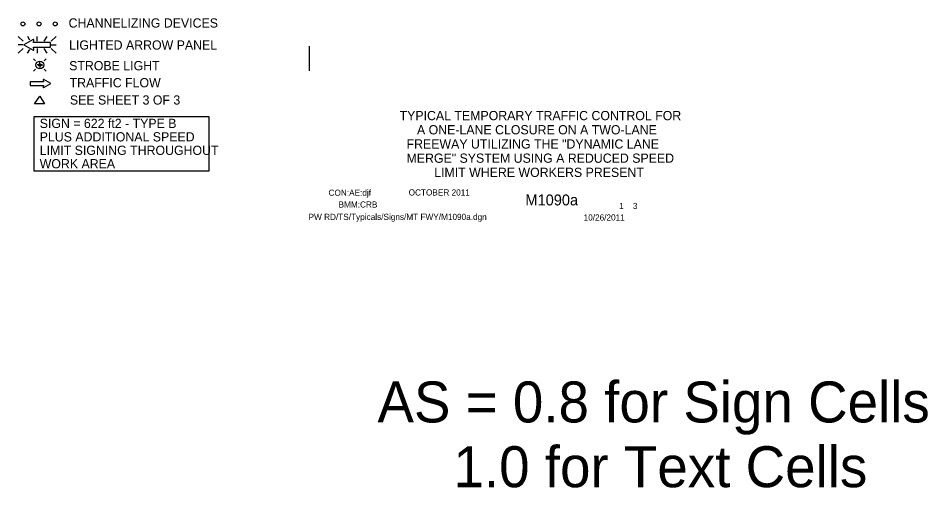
# Model space of a CAD drawing. Extents: x 15278 to 18126, y 1908 to 6555.
# Drawn here: x 15297 to 16214, y 1908 to 2381 of the extents above; entities that cross this region are included whole.
import ezdxf

# ---------------------------------------------------------------- set-up
doc = ezdxf.new("R2010")
doc.units = 0
for name, color, linetype in [('ALI_LEGAL_EX', 7, 'Continuous'), ('BORDER_SIGNAL_WO', 7, 'Continuous'), ('MT_SCRATCH_LEVEL_E', 7, 'Continuous'), ('TRAFFIC_SIGNS_PR', 7, 'Continuous'), ('TYPICAL_TEXT_DIMEN_EX', 7, 'Continuous'), ('TYPICAL_TEXT_DIMEN_PR', 7, 'Continuous')]:
    doc.layers.add(name, color=color, linetype=linetype)

msp = doc.modelspace()

# ---------------------------------------------------------------- linework, layer by layer
at = {"layer": 'ALI_LEGAL_EX'}
msp.add_lwpolyline([(15590.81, 2328.27), (15590.81, 2353.27)], dxfattribs=at)
at = {"layer": 'MT_SCRATCH_LEVEL_E'}
for p, q in [((15322.49, 2317.37), (15309.23, 2317.37)), ((15309.23, 2317.37), (15309.23, 2313.63)), ((15309.23, 2313.63), (15322.49, 2313.63)), ((15322.17, 2319.15), (15322.49, 2317.37)), ((15322.49, 2313.63), (15322.17, 2311.85)), ((15330.1, 2315.52), (15322.86, 2319.63)), ((15322.86, 2311.37), (15330.1, 2315.52))]:
    msp.add_line(p, q, dxfattribs=at)
for centre, start, end in [((15322.63, 2319.22), 60.42484, 189.96381), ((15322.63, 2311.78), 170.03619, 299.77312)]:
    msp.add_arc(centre, 0.463, start, end, dxfattribs=at)
at = {"layer": 'TRAFFIC_SIGNS_PR'}
for p, q in [((15297.1, 2362.98), (15302.03, 2358.05)), ((15308.86, 2359.16), (15306.66, 2362.99)), ((15316.18, 2358.05), (15316.18, 2362.99)), ((15323.42, 2358.05), (15326.27, 2362.99)), ((15330.33, 2358.05), (15335.27, 2362.99)), ((15302.03, 2354.49), (15297.1, 2354.49)), ((15297.1, 2346.01), (15302.03, 2350.94)), ((15306.61, 2346), (15308.72, 2349.67)), ((15316.18, 2350.94), (15316.18, 2346)), ((15326.31, 2346), (15323.46, 2350.94)), ((15330.33, 2354.49), (15335.27, 2354.49)), ((15330.33, 2350.94), (15335.27, 2346)), ((15314.69, 2338.46), (15312.66, 2340.49)), ((15323.25, 2338.46), (15325.29, 2340.49)), ((15314.69, 2329.9), (15312.66, 2327.87)), ((15318.97, 2334.18), (15316.09, 2334.18)), ((15318.97, 2334.18), (15318.97, 2337.06)), ((15318.97, 2334.18), (15318.97, 2330.24)), ((15318.97, 2334.18), (15321.85, 2334.18)), ((15325.29, 2327.87), (15323.25, 2329.9))]:
    msp.add_line(p, q, dxfattribs=at)
for points in [[(15312.11, 2359.77), (15302.82, 2354.49), (15312.11, 2349.17)], [(15312.99, 2349.8), (15312.59, 2352.07), (15329.6, 2352.07), (15329.6, 2356.87), (15312.59, 2356.87), (15312.99, 2359.15)]]:
    msp.add_lwpolyline(points, dxfattribs=at)
for centre, radius in [((15301.84, 2375.58), 2), ((15318.14, 2375.58), 2), ((15334.44, 2375.58), 2), ((15318.97, 2334.18), 3.94), ((15318.97, 2334.18), 1.28)]:
    msp.add_circle(centre, radius, dxfattribs=at)
for centre, radius, start, end in [((15312.4, 2359.25), 0.598, 350.73078, 118.89165), ((15312.4, 2349.7), 0.597, 241.48329, 9.95933)]:
    msp.add_arc(centre, radius, start, end, dxfattribs=at)
at = {"layer": 'TYPICAL_TEXT_DIMEN_EX'}
msp.add_lwpolyline([(15313.2, 2282.41), (15489.3, 2282.41), (15489.3, 2227.3), (15313.2, 2227.3)], close=True, dxfattribs=at)
at = {"layer": 'TYPICAL_TEXT_DIMEN_PR'}
msp.add_lwpolyline([(15313.43, 2294.94), (15318.89, 2302.82), (15323.52, 2294.94)], close=True, dxfattribs=at)

# ---------------------------------------------------------------- texts
at = {"layer": 'BORDER_SIGNAL_WO'}
for s, height, p in [('TYPICAL TEMPORARY TRAFFIC CONTROL FOR', 9.3, (15681.73, 2278.54)), ('A ONE-LANE CLOSURE ON A TWO-LANE', 9.3, (15699.24, 2264.24)), ('FREEWAY UTILIZING THE "DYNAMIC LANE', 9.3, (15688.74, 2249.94)), ('MERGE" SYSTEM USING A REDUCED SPEED', 9.3, (15688.7, 2235.64)), ('LIMIT WHERE WORKERS PRESENT', 9.3, (15716.6, 2221.34)), ('CON:AE:djf  ', 6.2, (15610.05, 2202.35)), ('    OCTOBER 2011    ', 6.2, (15681.62, 2202.63)), ('    M1090a   ', 11, (15792.22, 2192.67)), ('BMM:CRB   ', 6.2, (15620.17, 2190.46)), (' 1    3 ', 6.2, (15900.81, 2188.99)), ('PW RD/TS/Typicals/Signs/MT FWY/M1090a.dgn      ', 6.2, (15589.92, 2178)), ('10/26/2011    ', 6.2, (15867.29, 2177.42)), ('AS = 0.8 for Sign Cells', 41.2877, (15659.37, 1973.92)), ('     1.0 for Text Cells', 41.2877, (15659.37, 1908.64))]:
    msp.add_text(s, height=height, dxfattribs=at).set_placement(p)
at = {"layer": 'TYPICAL_TEXT_DIMEN_EX'}
for s, p in [('CHANNELIZING DEVICES', (15347.92, 2371.9)), ('LIGHTED ARROW PANEL', (15348.45, 2349.67)), ('STROBE LIGHT', (15348.5, 2328.86)), ('TRAFFIC FLOW', (15348.96, 2311.69)), ('SEE SHEET 3 OF 3', (15349.26, 2294.29)), ('SIGN = 622 ft2 - TYPE B', (15318.8, 2270.67)), ('PLUS ADDITIONAL SPEED', (15318.8, 2257.12)), ('LIMIT SIGNING THROUGHOUT', (15318.8, 2243.57)), ('WORK AREA', (15318.8, 2230.02))]:
    msp.add_text(s, height=9.3, dxfattribs=at).set_placement(p)

doc.saveas('drawing.dxf')
